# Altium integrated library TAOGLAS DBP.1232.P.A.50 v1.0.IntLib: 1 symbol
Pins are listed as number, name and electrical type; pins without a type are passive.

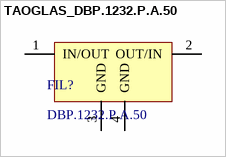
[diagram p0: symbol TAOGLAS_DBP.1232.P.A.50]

## TAOGLAS_DBP.1232.P.A.50
designator FIL?, comment DBP.1232.P.A.50
Dielectric Band Pass Filter for GPS L2/L5 Applications 4 Pole Bandwidth 136MHz; ComponentLibStatus: Created; MFG: Taoglas; Temp_High: +85C; Temp_Low: -40C
footprint TAOGLAS_DBP.1232.P.A.50 (Dielectric Band Pass Filter for GPS L2/L5 Applications 4 Pole Bandwidth 136MHz)
pins: 1 IN/OUT, 2 OUT/IN, 3 GND, 4 GND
